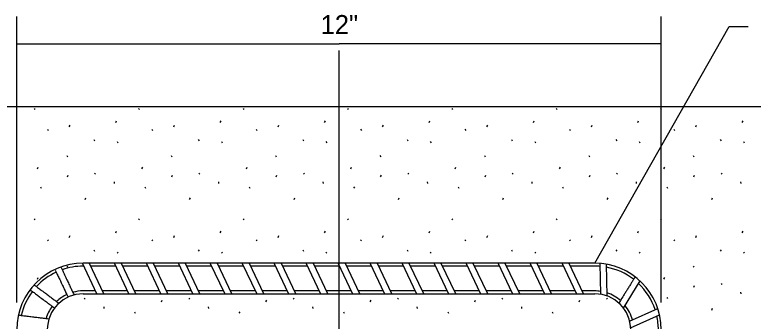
# Model space of a CAD drawing. Extents: x 99988 to 100172, y 99995 to 100047.
# Drawn here: x 100006.359 to 100009.065, y 100007.327 to 100008.45 of the extents above; entities that cross this region are included whole.
import ezdxf

# ---------------------------------------------------------------- set-up
doc = ezdxf.new("R2010")
doc.units = 0
for name, color, linetype in [('Level 1', 7, 'Continuous'), ('Level 10', 7, 'Continuous'), ('Level 15', 7, 'Continuous'), ('Level 20', 7, 'Continuous'), ('Level 3', 7, 'Continuous')]:
    doc.layers.add(name, color=color, linetype=linetype)

msp = doc.modelspace()

# ---------------------------------------------------------------- linework, layer by layer
at = {"layer": 'Level 1'}
msp.add_line((100000.585, 100008.1139), (100009.7707, 100008.1139), dxfattribs=at)
at = {"layer": 'Level 10'}
for p, q in [((100006.6601, 100007.4271), (100006.607, 100007.5394)), ((100008.4849, 100007.5394), (100006.6099, 100007.5394)), ((100006.6861, 100007.4271), (100006.6333, 100007.5387)), ((100006.7293, 100007.5287), (100006.638, 100007.5287)), ((100006.7773, 100007.4271), (100006.7242, 100007.5394)), ((100006.8033, 100007.4271), (100006.7504, 100007.5387)), ((100006.8465, 100007.5287), (100006.7552, 100007.5287)), ((100006.8945, 100007.4271), (100006.8414, 100007.5394)), ((100006.9204, 100007.4271), (100006.8676, 100007.5387)), ((100006.9637, 100007.5287), (100006.8724, 100007.5287)), ((100007.0117, 100007.4271), (100006.9586, 100007.5394)), ((100007.0376, 100007.4271), (100006.9848, 100007.5387)), ((100007.0808, 100007.5287), (100006.9896, 100007.5287)), ((100007.1286, 100007.4278), (100007.0758, 100007.5394)), ((100007.1548, 100007.4271), (100007.102, 100007.5387)), ((100007.198, 100007.5287), (100007.1068, 100007.5287)), ((100007.2458, 100007.4278), (100007.1929, 100007.5394)), ((100007.272, 100007.4271), (100007.2192, 100007.5387)), ((100007.3152, 100007.5287), (100007.224, 100007.5287)), ((100007.3629, 100007.4278), (100007.3101, 100007.5394)), ((100007.3892, 100007.4271), (100007.3364, 100007.5387)), ((100007.4324, 100007.5287), (100007.3411, 100007.5287)), ((100007.4801, 100007.4278), (100007.4273, 100007.5394)), ((100007.5064, 100007.4271), (100007.4536, 100007.5387)), ((100007.5496, 100007.5287), (100007.4583, 100007.5287)), ((100007.5973, 100007.4278), (100007.5445, 100007.5394)), ((100007.6236, 100007.4271), (100007.5708, 100007.5387)), ((100007.6668, 100007.5287), (100007.5755, 100007.5287)), ((100007.7145, 100007.4278), (100007.6617, 100007.5394)), ((100007.7408, 100007.4271), (100007.6879, 100007.5387)), ((100007.784, 100007.5287), (100007.6927, 100007.5287)), ((100007.8317, 100007.4278), (100007.7789, 100007.5394)), ((100007.8579, 100007.4271), (100007.8051, 100007.5387)), ((100007.9012, 100007.5287), (100007.8099, 100007.5287)), ((100007.9489, 100007.4278), (100007.8961, 100007.5394)), ((100007.9751, 100007.4271), (100007.9223, 100007.5387)), ((100008.0183, 100007.5287), (100007.9271, 100007.5287)), ((100008.0661, 100007.4278), (100008.0133, 100007.5394)), ((100008.0923, 100007.4271), (100008.0395, 100007.5387)), ((100008.1355, 100007.5287), (100008.0443, 100007.5287)), ((100008.1833, 100007.4278), (100008.1304, 100007.5394)), ((100008.2095, 100007.4271), (100008.1567, 100007.5387)), ((100008.2527, 100007.5287), (100008.1615, 100007.5287)), ((100008.3004, 100007.4278), (100008.2476, 100007.5394)), ((100008.3267, 100007.4271), (100008.2739, 100007.5387)), ((100008.3699, 100007.5287), (100008.2786, 100007.5287)), ((100008.4176, 100007.4278), (100008.3648, 100007.5394)), ((100008.4439, 100007.4271), (100008.3911, 100007.5387)), ((100008.4849, 100007.5287), (100008.3958, 100007.5287)), ((100008.5064, 100007.4254), (100008.5039, 100007.5387)), ((100008.53, 100007.4191), (100008.5274, 100007.5357)), ((100008.5897, 100007.3749), (100008.6508, 100007.4742)), ((100006.6551, 100007.4379), (100006.6099, 100007.4379)), ((100006.7722, 100007.4379), (100006.681, 100007.4379)), ((100006.8894, 100007.4379), (100006.7982, 100007.4379)), ((100007.0066, 100007.4379), (100006.9154, 100007.4379)), ((100007.1238, 100007.4379), (100007.0325, 100007.4379)), ((100007.241, 100007.4379), (100007.1497, 100007.4379)), ((100007.3582, 100007.4379), (100007.2669, 100007.4379)), ((100007.4754, 100007.4379), (100007.3841, 100007.4379)), ((100007.5926, 100007.4379), (100007.5013, 100007.4379)), ((100007.7097, 100007.4379), (100007.6185, 100007.4379)), ((100007.8269, 100007.4379), (100007.7357, 100007.4379)), ((100007.9441, 100007.4379), (100007.8529, 100007.4379)), ((100008.0613, 100007.4379), (100007.97, 100007.4379)), ((100008.1785, 100007.4379), (100008.0872, 100007.4379)), ((100008.2957, 100007.4379), (100008.2044, 100007.4379)), ((100008.4129, 100007.4379), (100008.3216, 100007.4379)), ((100008.4849, 100007.4379), (100008.4388, 100007.4379)), ((100006.6099, 100007.4271), (100008.4849, 100007.4271)), ((100008.6125, 100007.3268), (100008.7157, 100007.3736)), ((100008.6161, 100007.3027), (100008.7222, 100007.3508))]:
    msp.add_line(p, q, dxfattribs=at)
for centre, radius, start, end in [((100006.6099, 100007.2958), 0.2436, 90, 180), ((100006.6099, 100007.2958), 0.2329, 90, 109.3404), ((100008.4849, 100007.2958), 0.2436, 0, 90), ((100008.4849, 100007.2958), 0.2329, 85.2556, 90), ((100008.4849, 100007.2958), 0.2329, 52.3941, 79.416), ((100006.6099, 100007.2958), 0.2329, 115.1174, 137.2589), ((100008.4849, 100007.2958), 0.2329, 18.37, 46.5545), ((100006.6099, 100007.2958), 0.2329, 143.036, 166.9788), ((100006.6099, 100007.2958), 0.1421, 90, 105.486), ((100008.4849, 100007.2958), 0.1421, 81.3819, 90), ((100006.6099, 100007.2958), 0.1314, 90, 180), ((100006.6099, 100007.2958), 0.1421, 114.9836, 133.4046), ((100008.4849, 100007.2958), 0.1314, 0, 90), ((100008.4849, 100007.2958), 0.1421, 48.5203, 71.5972), ((100006.6099, 100007.2958), 0.1421, 142.9022, 163.1244), ((100008.4849, 100007.2958), 0.1421, 14.4962, 38.7357), ((100008.4849, 100007.2958), 0.2329, 0, 12.5304)]:
    msp.add_arc(centre, radius, start, end, dxfattribs=at)
for points in [[(100006.5284, 100007.5247), (100006.5289, 100007.5237), (100006.5298, 100007.5217), (100006.5326, 100007.5158), (100006.5345, 100007.5119), (100006.5388, 100007.5027), (100006.5413, 100007.4974), (100006.5466, 100007.4862), (100006.5495, 100007.4801), (100006.558, 100007.4621), (100006.5637, 100007.4501), (100006.5706, 100007.4354), (100006.5728, 100007.4309), (100006.5765, 100007.4228)], [(100008.5274, 100007.535), (100008.5274, 100007.535), (100008.5274, 100007.535), (100008.5274, 100007.5349), (100008.5274, 100007.5348), (100008.5274, 100007.5345), (100008.5274, 100007.5341), (100008.5274, 100007.5339), (100008.5274, 100007.5336), (100008.5275, 100007.5333)], [(100006.5074, 100007.5142), (100006.5082, 100007.5126), (100006.5094, 100007.51), (100006.5126, 100007.5034), (100006.5145, 100007.4992), (100006.5189, 100007.4899), (100006.5214, 100007.4846), (100006.5266, 100007.4737), (100006.5294, 100007.4679), (100006.5347, 100007.4565), (100006.5374, 100007.4509), (100006.5423, 100007.4404), (100006.5447, 100007.4356), (100006.549, 100007.4264), (100006.5509, 100007.4224), (100006.5548, 100007.415)], [(100008.6323, 100007.4889), (100008.6319, 100007.4883), (100008.6312, 100007.4871), (100008.6293, 100007.484), (100008.628, 100007.482), (100008.625, 100007.4771), (100008.6233, 100007.4743), (100008.6195, 100007.468), (100008.6173, 100007.4646), (100008.6129, 100007.4573), (100008.6105, 100007.4535), (100008.6057, 100007.4456), (100008.6033, 100007.4417), (100008.5961, 100007.43), (100008.5914, 100007.4224), (100008.5731, 100007.3931)], [(100006.4149, 100007.4419), (100006.4236, 100007.436), (100006.4285, 100007.4323), (100006.4428, 100007.4216), (100006.4531, 100007.4139), (100006.4732, 100007.3989), (100006.4831, 100007.3915), (100006.4947, 100007.3828), (100006.4982, 100007.3803), (100006.5053, 100007.3753)], [(100006.4302, 100007.4603), (100006.433, 100007.4582), (100006.4351, 100007.4566), (100006.4386, 100007.454), (100006.442, 100007.4514), (100006.4501, 100007.4454), (100006.4549, 100007.4418), (100006.4648, 100007.4344), (100006.4702, 100007.4304), (100006.4862, 100007.4185), (100006.4968, 100007.4105), (100006.51, 100007.4007), (100006.5141, 100007.3976), (100006.5211, 100007.3926)], [(100006.3723, 100007.3497), (100006.3767, 100007.349), (100006.378, 100007.3489), (100006.3826, 100007.3483), (100006.387, 100007.3477), (100006.397, 100007.3465), (100006.4028, 100007.3458), (100006.4152, 100007.3443), (100006.4218, 100007.3434), (100006.4416, 100007.341), (100006.4548, 100007.3394), (100006.4714, 100007.3373), (100006.4767, 100007.3367), (100006.4847, 100007.3357)]]:
    msp.add_open_spline(points, degree=3, dxfattribs=at)
at = {"layer": 'Level 15'}
for p, q in [((100006.3662, 100007.3958), (100006.3662, 100008.4439)), ((100008.7285, 100007.3958), (100008.7285, 100008.4439)), ((100006.3662, 100008.3439), (100007.5474, 100008.3439)), ((100008.7285, 100008.3439), (100007.5474, 100008.3439)), ((100007.5474, 100006.9869), (100007.5474, 100008.3189))]:
    msp.add_line(p, q, dxfattribs=at)
msp.add_lwpolyline([(100008.4849, 100007.5394), (100008.977, 100008.407), (100009.047, 100008.407)], dxfattribs=at)
at = {"layer": 'Level 3'}
for p, q in [((100006.4303, 100008.1069), (100006.4332, 100008.1026)), ((100006.813, 100008.1069), (100006.8158, 100008.1026)), ((100007.1956, 100008.1069), (100007.1985, 100008.1026)), ((100007.5782, 100008.1069), (100007.5811, 100008.1026)), ((100007.9609, 100008.1069), (100007.9638, 100008.1026)), ((100008.3435, 100008.1069), (100008.3464, 100008.1026)), ((100008.7262, 100008.1069), (100008.729, 100008.1026)), ((100006.7296, 100008.0553), (100006.7324, 100008.0617)), ((100007.1122, 100008.0553), (100007.1151, 100008.0617)), ((100007.4948, 100008.0553), (100007.4977, 100008.0617)), ((100007.8775, 100008.0553), (100007.8804, 100008.0617)), ((100008.2601, 100008.0553), (100008.263, 100008.0617)), ((100008.6428, 100008.0553), (100008.6456, 100008.0617)), ((100009.0254, 100008.0553), (100009.0283, 100008.0617)), ((100006.4786, 100008.0303), (100006.4815, 100008.026)), ((100006.5591, 100008.0387), (100006.562, 100008.0452)), ((100006.8612, 100008.0303), (100006.8641, 100008.026)), ((100006.9417, 100008.0387), (100006.9446, 100008.0452)), ((100007.2439, 100008.0303), (100007.2467, 100008.026)), ((100007.3244, 100008.0387), (100007.3272, 100008.0452)), ((100007.6265, 100008.0303), (100007.6294, 100008.026)), ((100007.707, 100008.0387), (100007.7099, 100008.0452)), ((100008.0091, 100008.0303), (100008.012, 100008.026)), ((100008.0896, 100008.0387), (100008.0925, 100008.0452)), ((100008.3918, 100008.0303), (100008.3947, 100008.026)), ((100008.4723, 100008.0387), (100008.4752, 100008.0452)), ((100008.7744, 100008.0303), (100008.7773, 100008.026)), ((100008.8549, 100008.0387), (100008.8578, 100008.0452)), ((100006.649, 100007.9927), (100006.6519, 100007.9884)), ((100006.734, 100007.9849), (100006.7369, 100007.9806)), ((100007.0316, 100007.9927), (100007.0345, 100007.9884)), ((100007.1166, 100007.9849), (100007.1195, 100007.9806)), ((100007.4143, 100007.9927), (100007.4172, 100007.9884)), ((100007.4993, 100007.9849), (100007.5022, 100007.9806)), ((100007.7969, 100007.9927), (100007.7998, 100007.9884)), ((100007.8819, 100007.9849), (100007.8848, 100007.9806)), ((100008.1796, 100007.9927), (100008.1824, 100007.9884)), ((100008.2646, 100007.9849), (100008.2674, 100007.9806)), ((100008.5622, 100007.9927), (100008.5651, 100007.9884)), ((100008.6472, 100007.9849), (100008.6501, 100007.9806)), ((100008.9448, 100007.9927), (100008.9477, 100007.9884)), ((100009.0298, 100007.9849), (100009.0327, 100007.9806)), ((100006.5495, 100007.9338), (100006.5524, 100007.9295)), ((100006.9322, 100007.9338), (100006.935, 100007.9295)), ((100007.3148, 100007.9338), (100007.3177, 100007.9295)), ((100007.6974, 100007.9338), (100007.7003, 100007.9295)), ((100008.0801, 100007.9338), (100008.083, 100007.9295)), ((100008.4627, 100007.9338), (100008.4656, 100007.9295)), ((100008.8454, 100007.9338), (100008.8482, 100007.9295)), ((100006.4426, 100007.8855), (100006.4454, 100007.892)), ((100006.6517, 100007.87), (100006.6546, 100007.8656)), ((100006.8252, 100007.8855), (100006.8281, 100007.892)), ((100007.0343, 100007.87), (100007.0372, 100007.8656)), ((100007.2078, 100007.8855), (100007.2107, 100007.892)), ((100007.417, 100007.87), (100007.4199, 100007.8656)), ((100007.5905, 100007.8855), (100007.5934, 100007.892)), ((100007.7996, 100007.87), (100007.8025, 100007.8656)), ((100007.9731, 100007.8855), (100007.976, 100007.892)), ((100008.1823, 100007.87), (100008.1851, 100007.8656)), ((100008.3558, 100007.8855), (100008.3586, 100007.892)), ((100008.5649, 100007.87), (100008.5678, 100007.8656)), ((100008.7384, 100007.8855), (100008.7413, 100007.892)), ((100008.9475, 100007.87), (100008.9504, 100007.8656)), ((100006.5519, 100007.856), (100006.5548, 100007.8625)), ((100006.9345, 100007.856), (100006.9374, 100007.8625)), ((100007.3172, 100007.856), (100007.3201, 100007.8625)), ((100007.6998, 100007.856), (100007.7027, 100007.8625)), ((100008.0825, 100007.856), (100008.0853, 100007.8625)), ((100008.4651, 100007.856), (100008.468, 100007.8625)), ((100008.8477, 100007.856), (100008.8506, 100007.8625)), ((100006.453, 100007.8189), (100006.4559, 100007.8146)), ((100006.7229, 100007.8379), (100006.7236, 100007.8315)), ((100006.8357, 100007.8189), (100006.8385, 100007.8146)), ((100007.1055, 100007.8379), (100007.1063, 100007.8315)), ((100007.2183, 100007.8189), (100007.2212, 100007.8146)), ((100007.4882, 100007.8379), (100007.4889, 100007.8315)), ((100007.601, 100007.8189), (100007.6038, 100007.8146)), ((100007.8708, 100007.8379), (100007.8715, 100007.8315)), ((100007.9836, 100007.8189), (100007.9865, 100007.8146)), ((100008.2535, 100007.8379), (100008.2542, 100007.8315)), ((100008.3662, 100007.8189), (100008.3691, 100007.8146)), ((100008.6361, 100007.8379), (100008.6368, 100007.8315)), ((100008.7489, 100007.8189), (100008.7517, 100007.8146)), ((100009.0187, 100007.8379), (100009.0195, 100007.8315)), ((100006.6174, 100007.7726), (100006.6202, 100007.779)), ((100007, 100007.7726), (100007.0029, 100007.779)), ((100007.3826, 100007.7726), (100007.3855, 100007.779)), ((100007.7653, 100007.7726), (100007.7682, 100007.779)), ((100008.1479, 100007.7726), (100008.1508, 100007.779)), ((100008.5306, 100007.7726), (100008.5334, 100007.779)), ((100008.9132, 100007.7726), (100008.9161, 100007.779)), ((100006.4303, 100007.7022), (100006.4332, 100007.6979)), ((100006.813, 100007.7022), (100006.8158, 100007.6979)), ((100007.1956, 100007.7022), (100007.1985, 100007.6979)), ((100007.5782, 100007.7022), (100007.5811, 100007.6979)), ((100007.9609, 100007.7022), (100007.9638, 100007.6979)), ((100008.3435, 100007.7022), (100008.3464, 100007.6979)), ((100008.7262, 100007.7022), (100008.729, 100007.6979)), ((100006.7296, 100007.6505), (100006.7324, 100007.657)), ((100007.1122, 100007.6505), (100007.1151, 100007.657)), ((100007.4948, 100007.6505), (100007.4977, 100007.657)), ((100007.8775, 100007.6505), (100007.8804, 100007.657)), ((100008.2601, 100007.6505), (100008.263, 100007.657)), ((100008.6428, 100007.6505), (100008.6456, 100007.657)), ((100009.0254, 100007.6505), (100009.0283, 100007.657)), ((100006.4786, 100007.6256), (100006.4815, 100007.6213)), ((100006.5591, 100007.634), (100006.562, 100007.6405)), ((100006.8612, 100007.6256), (100006.8641, 100007.6213)), ((100006.9417, 100007.634), (100006.9446, 100007.6405)), ((100007.2439, 100007.6256), (100007.2467, 100007.6213)), ((100007.3244, 100007.634), (100007.3272, 100007.6405)), ((100007.6265, 100007.6256), (100007.6294, 100007.6213)), ((100007.707, 100007.634), (100007.7099, 100007.6405)), ((100008.0091, 100007.6256), (100008.012, 100007.6213)), ((100008.0896, 100007.634), (100008.0925, 100007.6405)), ((100008.3918, 100007.6256), (100008.3947, 100007.6213)), ((100008.4723, 100007.634), (100008.4752, 100007.6405)), ((100008.7744, 100007.6256), (100008.7773, 100007.6213)), ((100008.8549, 100007.634), (100008.8578, 100007.6405)), ((100006.649, 100007.588), (100006.6519, 100007.5836)), ((100006.734, 100007.5802), (100006.7369, 100007.5759)), ((100007.0316, 100007.588), (100007.0345, 100007.5836)), ((100007.1166, 100007.5802), (100007.1195, 100007.5759)), ((100007.4143, 100007.588), (100007.4172, 100007.5836)), ((100007.4993, 100007.5802), (100007.5022, 100007.5759)), ((100007.7969, 100007.588), (100007.7998, 100007.5836)), ((100007.8819, 100007.5802), (100007.8848, 100007.5759)), ((100008.1796, 100007.588), (100008.1824, 100007.5836)), ((100008.2646, 100007.5802), (100008.2674, 100007.5759)), ((100008.5622, 100007.588), (100008.5651, 100007.5836)), ((100008.6472, 100007.5802), (100008.6501, 100007.5759)), ((100008.9448, 100007.588), (100008.9477, 100007.5836)), ((100009.0298, 100007.5802), (100009.0327, 100007.5759)), ((100006.5495, 100007.5291), (100006.5524, 100007.5248)), ((100008.8454, 100007.5291), (100008.8482, 100007.5248)), ((100006.4426, 100007.4808), (100006.4454, 100007.4873)), ((100008.7384, 100007.4808), (100008.7413, 100007.4873)), ((100008.9475, 100007.4652), (100008.9504, 100007.4609)), ((100008.8477, 100007.4513), (100008.8506, 100007.4578)), ((100006.6141, 100007.4117), (100006.617, 100007.4074)), ((100006.9968, 100007.4117), (100006.9996, 100007.4074)), ((100007.3794, 100007.4117), (100007.3823, 100007.4074)), ((100007.762, 100007.4117), (100007.7649, 100007.4074)), ((100008.1447, 100007.4117), (100008.1475, 100007.4074)), ((100008.5273, 100007.4117), (100008.5302, 100007.4074)), ((100008.7489, 100007.4142), (100008.7517, 100007.4098)), ((100009.0187, 100007.4332), (100009.0195, 100007.4268)), ((100006.8969, 100007.3978), (100006.8998, 100007.4042)), ((100007.2796, 100007.3978), (100007.2825, 100007.4042)), ((100007.6622, 100007.3978), (100007.6651, 100007.4042)), ((100008.0449, 100007.3978), (100008.0477, 100007.4042)), ((100008.4275, 100007.3978), (100008.4304, 100007.4042)), ((100006.6853, 100007.3797), (100006.686, 100007.3732)), ((100006.7981, 100007.3606), (100006.801, 100007.3563)), ((100007.068, 100007.3797), (100007.0687, 100007.3732)), ((100007.1807, 100007.3606), (100007.1836, 100007.3563)), ((100007.4506, 100007.3797), (100007.4513, 100007.3732)), ((100007.5634, 100007.3606), (100007.5662, 100007.3563)), ((100007.8332, 100007.3797), (100007.834, 100007.3732)), ((100007.946, 100007.3606), (100007.9489, 100007.3563)), ((100008.2159, 100007.3797), (100008.2166, 100007.3732)), ((100008.3286, 100007.3606), (100008.3315, 100007.3563)), ((100008.9132, 100007.3679), (100008.9161, 100007.3743))]:
    msp.add_line(p, q, dxfattribs=at)

# ---------------------------------------------------------------- texts
at = {"layer": 'Level 20'}
msp.add_text('12"', height=0.07, rotation=360, dxfattribs=at).set_placement((100007.48, 100008.3789))

doc.saveas('drawing.dxf')
